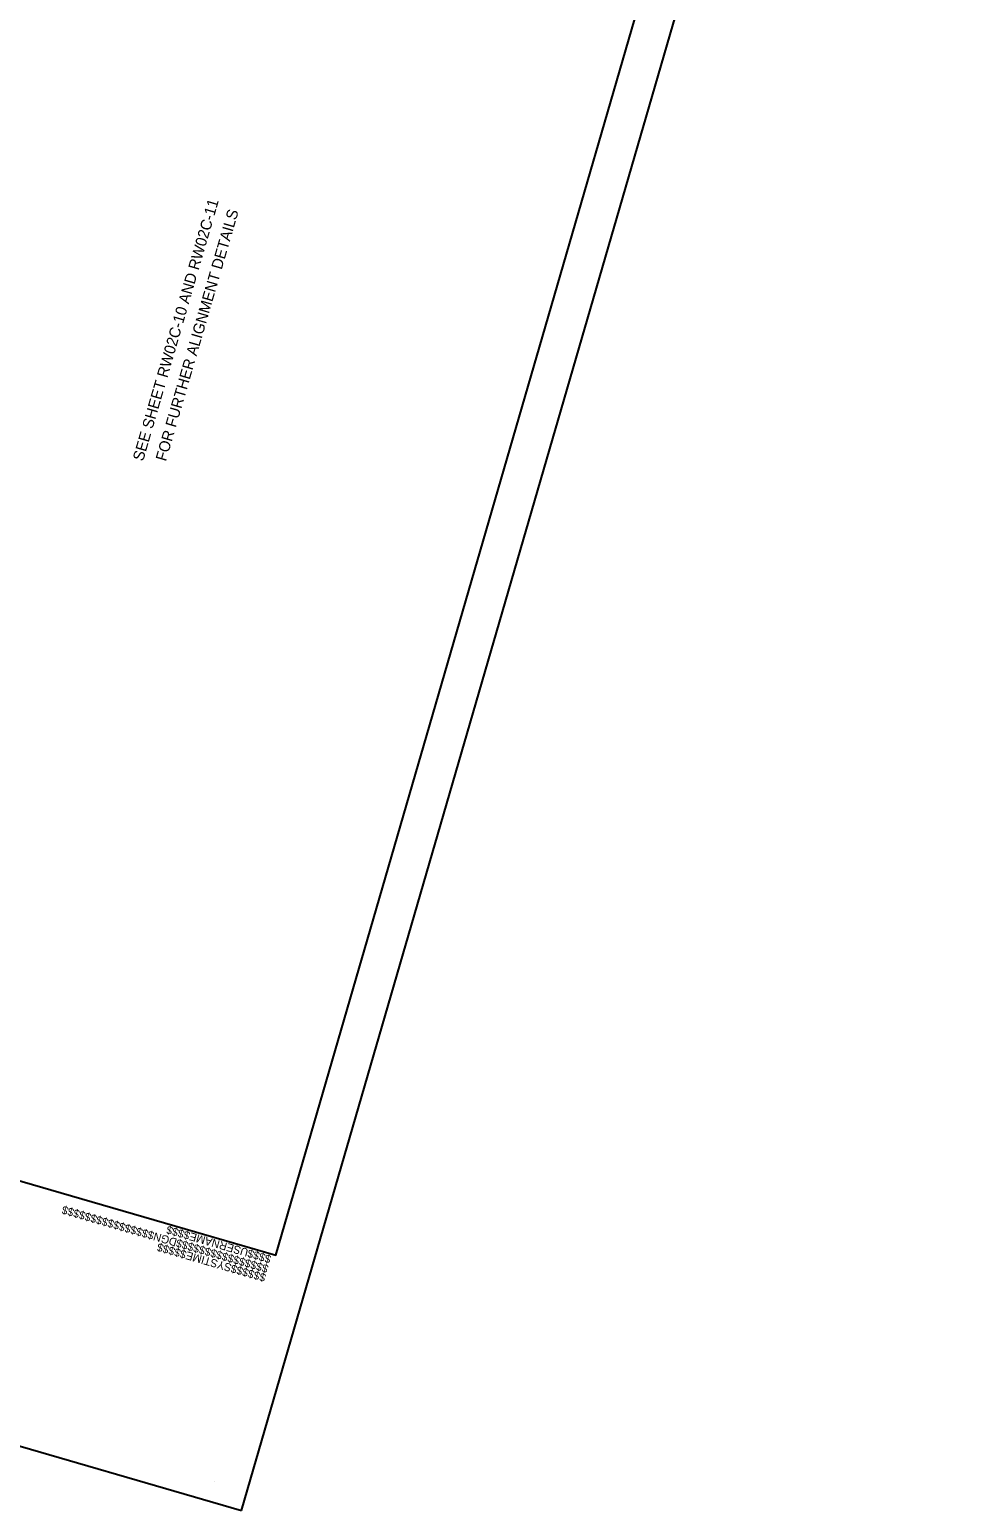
# Model space of a CAD drawing. Extents: x 479429 to 482809, y 488118 to 492379.
# Drawn here: x 481461 to 482809, y 488118 to 490269 of the extents above; entities that cross this region are included whole.
import ezdxf

# ---------------------------------------------------------------- set-up
doc = ezdxf.new("R2010")
doc.units = 0
for name, color, linetype in [('CTL Sheet Border CELL', 7, 'Continuous'), ('CTL Sheet Notes CELL', 7, 'Continuous'), ('Sheet Plot Border Outside CELL', 7, 'Continuous')]:
    doc.layers.add(name, color=color, linetype=linetype)

msp = doc.modelspace()

# ---------------------------------------------------------------- linework, layer by layer
at = {"layer": 'CTL Sheet Border CELL'}
for p, q in [((481818.8, 488488.4), (481818.8, 488488.4)), ((481818.8, 488488.4), (481818.8, 488488.4)), ((481818.8, 488488.4), (481818.8, 488488.4)), ((481818.8, 488488.4), (481818.8, 488488.4)), ((481818.8, 488488.4), (481818.8, 488488.4)), ((481818.8, 488488.4), (481818.8, 488488.4)), ((481818.8, 488488.4), (481818.8, 488488.4)), ((481818.8, 488488.4), (481818.8, 488488.4)), ((481818.8, 488488.4), (481818.8, 488488.4)), ((481818.8, 488488.4), (481818.8, 488488.4)), ((481818.8, 488488.4), (481818.8, 488488.4)), ((481729.2, 488159.3), (481729.2, 488159.3)), ((481768.9, 488117.8), (481768.9, 488117.8))]:
    msp.add_line(p, q, dxfattribs=at)
msp.add_lwpolyline([(480512.1, 492327.1), (479585.7, 489136.9), (481818.8, 488488.4), (482745.3, 491678.6)], close=True, dxfattribs=at)
msp.add_lwpolyline([(481842, 488568.2), (481842, 488568.2)], dxfattribs=at)
msp.add_lwpolyline([(481842, 488568.2), (481842, 488568.2)], dxfattribs=at)
at = {"layer": 'Sheet Plot Border Outside CELL'}
msp.add_lwpolyline([(481768.9, 488117.8), (482808.9, 491699.3), (480469.5, 492378.7), (479429.4, 488797.2)], close=True, dxfattribs=at)

# ---------------------------------------------------------------- texts
at = {"layer": 'CTL Sheet Border CELL'}
for s, p in [('$$$$$$$$$$$$$$$$DGN$$$$$$$$$$$$$$$$', (481809.1, 488473.6)), ('$$$$USERNAME$$$$', (481813.1, 488487.6)), ('$$$$$$SYSTIME$$$$$', (481805.4, 488460.7))]:
    msp.add_text(s, height=11.627, rotation=163.8071, dxfattribs=at).set_placement(p)
at = {"layer": 'CTL Sheet Notes CELL'}
for s, p in [('SEE SHEET RW02C-10 AND RW02C-11', (481626, 489640.9)), ('FOR FURTHER ALIGNMENT DETAILS', (481659.2, 489640.7))]:
    msp.add_text(s, height=16, rotation=73.8069, dxfattribs=at).set_placement(p)

doc.saveas('drawing.dxf')
